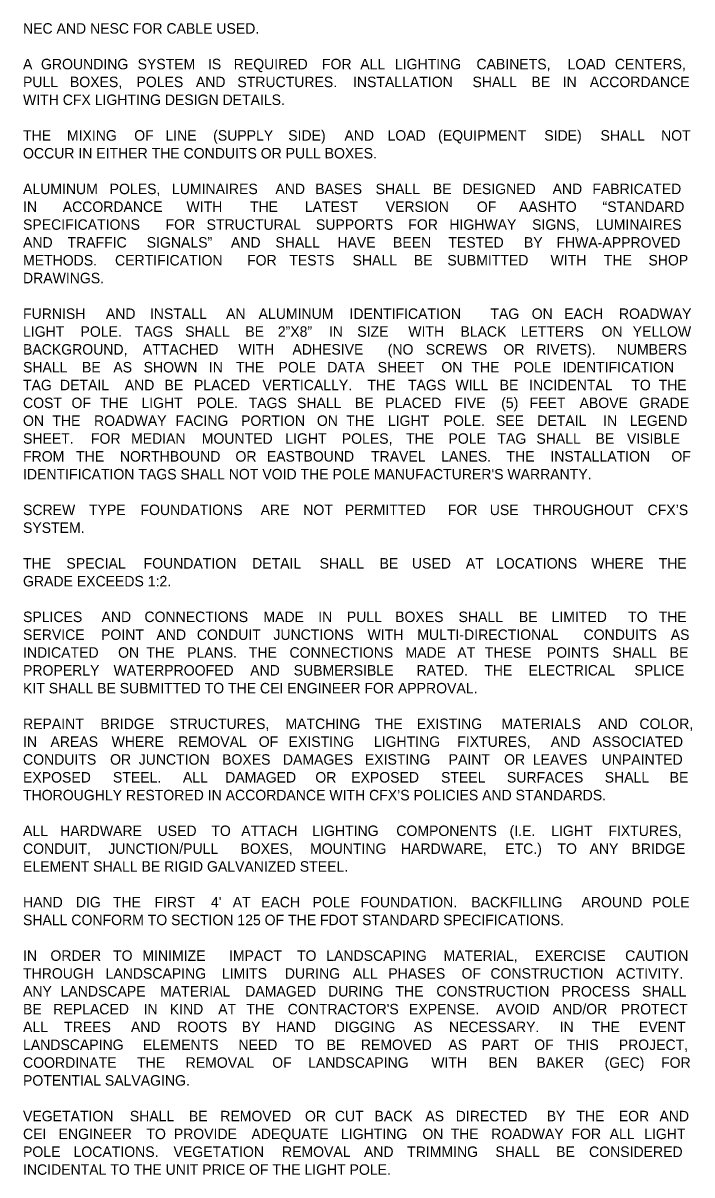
# Model space of a CAD drawing. Extents: x -55 to 2471539, y -90 to 3608906.
# Drawn here: x 568 to 1014, y 8 to 777 of the extents above; entities that cross this region are included whole.
import ezdxf

# ---------------------------------------------------------------- set-up
doc = ezdxf.new("R2010")
doc.units = 0
doc.layers.add('XSCell', color=7, linetype='Continuous')

msp = doc.modelspace()

# ---------------------------------------------------------------- texts
at = {"layer": 'XSCell'}
for s, p in [('NEC AND NESC FOR CABLE USED.', (568.01, 770.14)), ('GROUNDING ', (580.01, 746.34)), ('SYSTEM ', (644.47, 746.34)), ('IS ', (691.38, 746.34)), ('REQUIRED ', (708.58, 746.34)), ('FOR ', (767.49, 746.34)), ('LIGHTING ', (816.15, 746.34)), ('CABINETS, ', (870.55, 746.34)), ('LOAD ', (931.31, 746.34)), ('CENTERS, ', (962.92, 746.34)), ('A ', (568.01, 746.34)), ('ALL ', (793.05, 746.34)), ('PULL ', (568.01, 734.44)), ('BOXES, ', (599.32, 734.44)), ('POLES ', (643.71, 734.44)), ('AND ', (683.35, 734.44)), ('STRUCTURES. ', (711.03, 734.44)), ('INSTALLATION ', (788.2, 734.44)), ('SHALL ', (867.91, 734.44)), ('BE ', (907.21, 734.44)), ('IN ', (928.07, 734.44)), ('ACCORDANCE ', (946.18, 734.44)), ('WITH CFX LIGHTING DESIGN DETAILS.', (568.01, 722.54)), ('THE ', (568.01, 698.74)), ('MIXING ', (597.31, 698.74)), ('OF ', (642.19, 698.74)), ('LINE ', (663, 698.74)), ('(SUPPLY ', (694.88, 698.74)), ('SIDE) ', (744.95, 698.74)), ('AND ', (782.46, 698.74)), ('LOAD ', (811.22, 698.74)), ('(EQUIPMENT ', (844.96, 698.74)), ('SIDE) ', (915.82, 698.74)), ('SHALL ', (953.33, 698.74)), ('NOT ', (993.71, 698.74)), ('OCCUR IN EITHER THE CONDUITS OR PULL BOXES.', (568.01, 686.84)), ('ALUMINUM ', (568.01, 663.04)), ('POLES, ', (625.83, 663.04)), ('LUMINAIRES ', (667.41, 663.04)), ('AND ', (736.42, 663.04)), ('BASES ', (762.98, 663.04)), ('SHALL ', (803.29, 663.04)), ('BE ', (841.48, 663.04)), ('DESIGNED ', (861.21, 663.04)), ('AND ', (921.34, 663.04)), ('FABRICATED ', (947.9, 663.04)), ('IN ', (568.01, 651.14)), ('ACCORDANCE ', (594.51, 651.14)), ('WITH ', (677.06, 651.14)), ('THE ', (719.43, 651.14)), ('LATEST ', (756.05, 651.14)), ('VERSION ', (810.01, 651.14)), ('OF ', (870.8, 651.14)), ('AASHTO ', (898.93, 651.14)), ('“STANDARD ', (954.69, 651.14)), ('SPECIFICATIONS ', (568.01, 639.24)), ('FOR ', (663.12, 639.24)), ('STRUCTURAL ', (690.51, 639.24)), ('SUPPORTS ', (763.45, 639.24)), ('FOR ', (825.09, 639.24)), ('HIGHWAY ', (852.48, 639.24)), ('SIGNS, ', (907.69, 639.24)), ('LUMINAIRES ', (950.21, 639.24)), ('AND ', (568.01, 627.34)), ('TRAFFIC ', (597.7, 627.34)), ('SIGNALS” ', (650.56, 627.34)), ('AND ', (706.75, 627.34)), ('SHALL ', (736.44, 627.34)), ('HAVE ', (777.76, 627.34)), ('BEEN ', (814.87, 627.34)), ('TESTED ', (851.81, 627.34)), ('BY ', (902.26, 627.34)), ('FHWA-APPROVED ', (923.92, 627.34)), ('METHODS. ', (568.01, 615.44)), ('CERTIFICATION ', (629.39, 615.44)), ('FOR ', (717.5, 615.44)), ('TESTS ', (745.65, 615.44)), ('SHALL ', (787.89, 615.44)), ('BE ', (828.73, 615.44)), ('SUBMITTED ', (851.14, 615.44)), ('WITH ', (920.02, 615.44)), ('THE ', (955.54, 615.44)), ('SHOP ', (985.31, 615.44)), ('DRAWINGS.', (568.01, 603.54)), ('FURNISH ', (568.01, 579.74)), ('AND ', (623.29, 579.74)), ('INSTALL ', (652.69, 579.74)), ('AN ', (703.49, 579.74)), ('ALUMINUM ', (725.21, 579.74)), ('IDENTIFICATION ', (785.87, 579.74)), ('TAG ', (879.86, 579.74)), ('ON ', (907.43, 579.74)), ('EACH ', (929.1, 579.74)), ('ROADWAY ', (965.64, 579.74)), ('LIGHT ', (568.01, 567.84)), ('POLE. ', (606.39, 567.84)), ('TAGS ', (642.51, 567.84)), ('SHALL ', (676.24, 567.84)), ('BE ', (716.34, 567.84)), ('2”X8” ', (738.01, 567.84)), ('IN ', (772.11, 567.84)), ('SIZE ', (791.03, 567.84)), ('WITH ', (825.09, 567.84)), ('BLACK ', (859.87, 567.84)), ('LETTERS ', (900.07, 567.84)), ('ON ', (954.05, 567.84)), ('YELLOW ', (974.8, 567.84)), ('BACKGROUND, ', (568.01, 555.94)), ('ATTACHED ', (647.98, 555.94)), ('WITH ', (711.72, 555.94)), ('ADHESIVE ', (747.77, 555.94)), ('(NO ', (811.36, 555.94)), ('SCREWS ', (836.74, 555.94)), ('OR ', (888.54, 555.94)), ('RIVETS). ', (910.5, 555.94)), ('NUMBERS ', (964.15, 555.94)), ('SHALL ', (568.01, 544.04)), ('BE ', (607.37, 544.04)), ('AS ', (628.28, 544.04)), ('SHOWN ', (648.48, 544.04)), ('IN ', (691.99, 544.04)), ('THE ', (710.16, 544.04)), ('POLE ', (738.44, 544.04)), ('DATA ', (771.06, 544.04)), ('SHEET ', (804.66, 544.04)), ('ON ', (847.15, 544.04)), ('THE ', (867.16, 544.04)), ('POLE ', (895.44, 544.04)), ('IDENTIFICATION ', (928.06, 544.04)), ('TAG ', (568.01, 532.14)), ('DETAIL ', (592.69, 532.14)), ('AND ', (635.86, 532.14)), ('BE ', (662.38, 532.14)), ('PLACED ', (682.08, 532.14)), ('VERTICALLY. ', (727.77, 532.14)), ('THE ', (797.76, 532.14)), ('TAGS ', (824.83, 532.14)), ('WILL ', (856.59, 532.14)), ('BE ', (886.05, 532.14)), ('INCIDENTAL ', (905.75, 532.14)), ('TO ', (973.89, 532.14)), ('THE ', (992.12, 532.14)), ('COST ', (568.01, 520.24)), ('OF ', (600.37, 520.24)), ('THE ', (619.44, 520.24)), ('LIGHT ', (647, 520.24)), ('POLE. ', (683.91, 520.24)), ('TAGS ', (718.57, 520.24)), ('SHALL ', (750.83, 520.24)), ('BE ', (789.47, 520.24)), ('PLACED ', (809.66, 520.24)), ('FIVE ', (855.85, 520.24)), ('(5) ', (887.05, 520.24)), ('FEET ', (906.02, 520.24)), ('ABOVE ', (939.36, 520.24)), ('GRADE ', (979.17, 520.24)), ('ON ', (568.01, 508.34)), ('THE ', (587.57, 508.34)), ('ROADWAY ', (615.39, 508.34)), ('FACING ', (669.69, 508.34)), ('PORTION ', (713.51, 508.34)), ('ON ', (764.09, 508.34)), ('THE ', (783.65, 508.34)), ('LIGHT ', (811.48, 508.34)), ('POLE. ', (848.66, 508.34)), ('SEE ', (883.58, 508.34)), ('DETAIL ', (911.18, 508.34)), ('IN ', (955.12, 508.34)), ('LEGEND ', (972.84, 508.34)), ('SHEET. ', (568.01, 496.44)), ('FOR ', (613.33, 496.44)), ('MEDIAN ', (640.07, 496.44)), ('MOUNTED ', (687.27, 496.44)), ('LIGHT ', (742.99, 496.44)), ('POLES, ', (780.69, 496.44)), ('THE ', (823.52, 496.44)), ('POLE ', (851.88, 496.44)), ('TAG ', (884.57, 496.44)), ('SHALL ', (910.54, 496.44)), ('BE ', (949.98, 496.44)), ('VISIBLE ', (970.96, 496.44)), ('FROM ', (568.01, 484.54)), ('THE ', (603.39, 484.54)), ('NORTHBOUND ', (632.65, 484.54)), ('OR ', (709.75, 484.54)), ('EASTBOUND ', (730.69, 484.54)), ('TRAVEL ', (800.16, 484.54)), ('LANES. ', (847.03, 484.54)), ('THE ', (890.59, 484.54)), ('INSTALLATION ', (919.86, 484.54)), ('OF ', (1000.61, 484.54)), ("IDENTIFICATION TAGS SHALL NOT VOID THE POLE MANUFACTURER'S WARRANTY.", (568.01, 472.64)), ('SCREW ', (568.01, 448.84)), ('TYPE ', (612.05, 448.84)), ('FOUNDATIONS ', (646.38, 448.84)), ('ARE ', (726.54, 448.84)), ('NOT ', (755, 448.84)), ('PERMITTED ', (782.71, 448.84)), ('FOR ', (851.45, 448.84)), ('USE ', (879.44, 448.84)), ('THROUGHOUT ', (908.4, 448.84)), ('CFX’S ', (984.76, 448.84)), ('SYSTEM.', (568.01, 436.94)), ('THE ', (568.01, 413.14)), ('SPECIAL ', (596.95, 413.14)), ('FOUNDATION ', (648.45, 413.14)), ('DETAIL ', (720.86, 413.14)), ('SHALL ', (765.91, 413.14)), ('BE ', (805.93, 413.14)), ('USED ', (827.51, 413.14)), ('AT ', (863.48, 413.14)), ('LOCATIONS ', (883.63, 413.14)), ('WHERE ', (947.18, 413.14)), ('THE ', (992.12, 413.14)), ('GRADE EXCEEDS 1:2.', (568.01, 401.24)), ('SPLICES ', (568.01, 377.44)), ('AND ', (620.4, 377.44)), ('CONNECTIONS ', (649.03, 377.44)), ('MADE ', (728.42, 377.44)), ('IN ', (764.98, 377.44)), ('PULL ', (784.04, 377.44)), ('BOXES ', (816.31, 377.44)), ('SHALL ', (858.59, 377.44)), ('BE ', (898.84, 377.44)), ('LIMITED ', (920.65, 377.44)), ('TO ', (971.78, 377.44)), ('THE ', (992.12, 377.44)), ('SERVICE ', (568.01, 365.54)), ('POINT ', (620.07, 365.54)), ('AND ', (657.06, 365.54)), ('CONDUIT ', (684.01, 365.54)), ('JUNCTIONS ', (735.09, 365.54)), ('WITH ', (797.86, 365.54)), ('MULTI-DIRECTIONAL ', (831.11, 365.54)), ('CONDUITS ', (942.04, 365.54)), ('AS ', (1000.2, 365.54)), ('INDICATED ', (568.01, 353.64)), ('ON ', (631.45, 353.64)), ('THE ', (650.33, 353.64)), ('PLANS. ', (677.5, 353.64)), ('THE ', (718.68, 353.64)), ('CONNECTIONS ', (745.84, 353.64)), ('MADE ', (823.22, 353.64)), ('AT ', (857.76, 353.64)), ('THESE ', (876.13, 353.64)), ('POINTS ', (917.5, 353.64)), ('SHALL ', (961.24, 353.64)), ('BE ', (999.48, 353.64)), ('PROPERLY ', (568.01, 341.74)), ('WATERPROOFED ', (628.45, 341.74)), ('AND ', (719.6, 341.74)), ('SUBMERSIBLE ', (748.61, 341.74)), ('RATED. ', (830.55, 341.74)), ('THE ', (875.77, 341.74)), ('ELECTRICAL ', (905.32, 341.74)), ('SPLICE ', (975.98, 341.74)), ('KIT SHALL BE SUBMITTED TO THE CEI ENGINEER FOR APPROVAL.', (568.01, 329.84)), ('REPAINT ', (568.01, 306.04)), ('BRIDGE ', (619.62, 306.04)), ('STRUCTURES, ', (665.82, 306.04)), ('MATCHING ', (743.13, 306.04)), ('THE ', (802.64, 306.04)), ('EXISTING ', (830.7, 306.04)), ('MATERIALS ', (887.2, 306.04)), ('AND ', (951.78, 306.04)), ('COLOR, ', (979.3, 306.04)), ('IN ', (568.01, 294.14)), ('AREAS ', (586.33, 294.14)), ('WHERE ', (627.11, 294.14)), ('REMOVAL ', (671.54, 294.14)), ('OF ', (725.3, 294.14)), ('EXISTING ', (745.24, 294.14)), ('LIGHTING ', (802.12, 294.14)), ('FIXTURES, ', (857.79, 294.14)), ('AND ', (920.15, 294.14)), ('ASSOCIATED ', (948.05, 294.14)), ('CONDUITS ', (568.01, 282.24)), ('OR ', (626.11, 282.24)), ('JUNCTION ', (645.22, 282.24)), ('BOXES ', (700.86, 282.24)), ('DAMAGES ', (741.4, 282.24)), ('EXISTING ', (796.13, 282.24)), ('PAINT ', (852.01, 282.24)), ('OR ', (888.99, 282.24)), ('LEAVES ', (908.1, 282.24)), ('UNPAINTED ', (954.1, 282.24)), ('EXPOSED ', (568.01, 270.34)), ('STEEL. ', (627.98, 270.34)), ('ALL ', (674.69, 270.34)), ('DAMAGED ', (702.88, 270.34)), ('OR ', (763.04, 270.34)), ('EXPOSED ', (786.96, 270.34)), ('STEEL ', (846.94, 270.34)), ('SURFACES ', (890.89, 270.34)), ('SHALL ', (956.14, 270.34)), ('BE ', (999.48, 270.34)), ('THOROUGHLY RESTORED IN ACCORDANCE WITH CFX’S POLICIES AND STANDARDS. ', (568.01, 258.44)), ('ALL ', (568.01, 234.64)), ('HARDWARE ', (592.75, 234.64)), ('USED ', (657.8, 234.64)), ('TO ', (693.63, 234.64)), ('ATTACH ', (713.61, 234.64)), ('LIGHTING ', (761.04, 234.64)), ('COMPONENTS ', (817.08, 234.64)), ('(I.E. ', (892.66, 234.64)), ('LIGHT ', (920.42, 234.64)), ('FIXTURES, ', (958.58, 234.64)), ('CONDUIT, ', (568.01, 222.74)), ('JUNCTION/PULL ', (624.91, 222.74)), ('BOXES, ', (713.12, 222.74)), ('MOUNTING ', (759.53, 222.74)), ('HARDWARE, ', (820.2, 222.74)), ('ETC.) ', (889.76, 222.74)), ('TO ', (924.61, 222.74)), ('ANY ', (946.03, 222.74)), ('BRIDGE ', (973.98, 222.74)), ('ELEMENT SHALL BE RIGID GALVANIZED STEEL.', (568.01, 210.84)), ('HAND ', (568.01, 187.04)), ('DIG ', (603.24, 187.04)), ('THE ', (627.99, 187.04)), ('FIRST ', (655.69, 187.04)), ("4' ", (693.4, 187.04)), ('AT ', (707.92, 187.04)), ('EACH ', (726.83, 187.04)), ('POLE ', (761.14, 187.04)), ('FOUNDATION. ', (793.18, 187.04)), ('BACKFILLING ', (867.11, 187.04)), ('AROUND ', (940.66, 187.04)), ('POLE ', (987.78, 187.04)), ('SHALL CONFORM TO SECTION 125 OF THE FDOT STANDARD SPECIFICATIONS.', (568.01, 175.14)), ('IN ', (568.01, 151.34)), ('ORDER ', (586.31, 151.34)), ('TO ', (628.08, 151.34)), ('MINIMIZE ', (647.66, 151.34)), ('IMPACT ', (705.48, 151.34)), ('TO ', (750.79, 151.34)), ('LANDSCAPING ', (770.36, 151.34)), ('MATERIAL, ', (848.58, 151.34)), ('EXERCISE ', (909.49, 151.34)), ('CAUTION ', (969.8, 151.34)), ('THROUGH ', (568.01, 139.44)), ('LANDSCAPING ', (623.09, 139.44)), ('LIMITS ', (700.68, 139.44)), ('DURING ', (742.68, 139.44)), ('ALL ', (788.03, 139.44)), ('PHASES ', (811.75, 139.44)), ('OF ', (860.6, 139.44)), ('CONSTRUCTION ', (879.89, 139.44)), ('ACTIVITY. ', (963.78, 139.44)), ('ANY ', (568.01, 127.54)), ('LANDSCAPE ', (593.07, 127.54)), ('MATERIAL ', (659.49, 127.54)), ('DAMAGED ', (716.29, 127.54)), ('DURING ', (771.54, 127.54)), ('THE ', (816.47, 127.54)), ('CONSTRUCTION ', (843.83, 127.54)), ('PROCESS ', (927.29, 127.54)), ('SHALL ', (981.03, 127.54)), ('BE ', (568.01, 115.64)), ('REPLACED ', (588.23, 115.64)), ('IN ', (648.46, 115.64)), ('KIND ', (665.93, 115.64)), ('AT ', (698.24, 115.64)), ('THE ', (717.04, 115.64)), ("CONTRACTOR'S ", (744.63, 115.64)), ('EXPENSE. ', (825.54, 115.64)), ('AVOID ', (883.61, 115.64)), ('AND/OR ', (921.45, 115.64)), ('PROTECT ', (966.83, 115.64)), ('ALL ', (568.01, 103.74)), ('TREES ', (595.45, 103.74)), ('AND ', (639.99, 103.74)), ('ROOTS ', (670.96, 103.74)), ('BY ', (713.96, 103.74)), ('HAND ', (736.91, 103.74)), ('DIGGING ', (775.95, 103.74)), ('AS ', (828.8, 103.74)), ('NECESSARY. ', (852.22, 103.74)), ('IN ', (926.06, 103.74)), ('THE ', (947.46, 103.74)), ('EVENT ', (978.98, 103.74)), ('LANDSCAPING ', (568.01, 91.84)), ('ELEMENTS ', (648.02, 91.84)), ('NEED ', (711.71, 91.84)), ('TO ', (749.23, 91.84)), ('BE ', (770.6, 91.84)), ('REMOVED ', (793.44, 91.84)), ('AS ', (851.82, 91.84)), ('PART ', (873.94, 91.84)), ('OF ', (909.09, 91.84)), ('THIS ', (930.81, 91.84)), ('PROJECT, ', (965.48, 91.84)), ('COORDINATE ', (568.01, 79.94)), ('THE ', (644.1, 79.94)), ('REMOVAL ', (676.52, 79.94)), ('OF ', (734.26, 79.94)), ('LANDSCAPING ', (758.19, 79.94)), ('WITH ', (840.42, 79.94)), ('BEN ', (878.59, 79.94)), ('BAKER ', (910.58, 79.94)), ('(GEC) ', (956.07, 79.94)), ('FOR ', (993.73, 79.94)), ('POTENTIAL SALVAGING.', (568.01, 68.04)), ('VEGETATION ', (568.01, 44.24)), ('SHALL ', (639.27, 44.24)), ('BE ', (678.67, 44.24)), ('REMOVED ', (699.63, 44.24)), ('OR ', (756.14, 44.24)), ('CUT ', (776.13, 44.24)), ('BACK ', (802.52, 44.24)), ('AS ', (836.47, 44.24)), ('DIRECTED ', (856.71, 44.24)), ('BY ', (917.44, 44.24)), ('THE ', (937.2, 44.24)), ('EOR ', (965.52, 44.24)), ('AND ', (992.65, 44.24)), ('CEI ', (568.01, 32.34)), ('ENGINEER ', (591.75, 32.34)), ('TO ', (650.35, 32.34)), ('PROVIDE ', (668.61, 32.34)), ('ADEQUATE ', (720.42, 32.34)), ('LIGHTING ', (780.17, 32.34)), ('ON ', (834.49, 32.34)), ('THE ', (853.31, 32.34)), ('ROADWAY ', (880.4, 32.34)), ('FOR ', (933.96, 32.34)), ('ALL ', (959.44, 32.34)), ('LIGHT ', (982.46, 32.34)), ('POLE ', (568.01, 20.44)), ('LOCATIONS. ', (601.72, 20.44)), ('VEGETATION ', (668.47, 20.44)), ('REMOVAL ', (740.78, 20.44)), ('AND ', (795.48, 20.44)), ('TRIMMING ', (824.32, 20.44)), ('SHALL ', (883.22, 20.44)), ('BE ', (923.68, 20.44)), ('CONSIDERED ', (945.69, 20.44)), ('INCIDENTAL TO THE UNIT PRICE OF THE LIGHT POLE.', (568.01, 8.54))]:
    msp.add_text(s, height=7, dxfattribs=at).set_placement(p)

doc.saveas('drawing.dxf')
